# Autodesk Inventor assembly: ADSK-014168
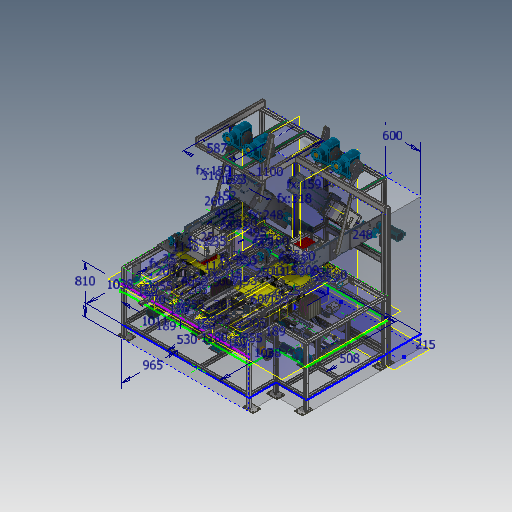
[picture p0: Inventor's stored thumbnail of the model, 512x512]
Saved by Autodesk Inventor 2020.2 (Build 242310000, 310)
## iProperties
Created: 2019-10
Part Number: ADSK-014168
Document SubType Name: Assembly
Designer: lutzd
Mass: 6.6352e+07 g
Surface Area: 1.07155e+06 cm^2
Volume: 8.52523e+06 cm^3
Density: 7.78302 g/cm^3
VLDS_Profile: Default Assembly
VLDS_TimeStamp: 2016-07-29
VLDS_FailCnt: 0
VLDS_AcceptCnt: 0
Dimensions: 2816,7x2637,5x2753,9 mm
Mass: 66352,024 kg
DocNumber: ADSK-014168
Folder: 01 - Themengebiete\Simplification\01 - Packaging machine\
VDS_Category: 3D Komponenten
VDS_NumSchm: Autodesk
Title: MOD-019310
Author: lutzd
Revision Number: -
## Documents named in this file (15)
- D:\07 - DEMODATEN\OTX 2019 - Dataset - UPDATE - Dez2019\Designs\07-Packing machine\ADSK-014168.iam
- D:\07 - DEMODATEN\OTX 2019 - Dataset - UPDATE - Dez2019\Designs\07-Packing machine\ADSK-014078.iam
- D:\07 - DEMODATEN\OTX 2019 - Dataset - UPDATE - Dez2019\Designs\07-Packing machine\SUB-129310.iam
- D:\07 - DEMODATEN\OTX 2019 - Dataset - UPDATE - Dez2019\Content Center Files\de-DE\DIN 125-1  B\DIN 125-1 - B 8,4.ipt
- D:\07 - DEMODATEN\OTX 2019 - Dataset - UPDATE - Dez2019\Content Center Files\de-DE\ISO 4762(2)\ISO 4762 - M8 x 20ISO.ipt
- D:\07 - DEMODATEN\OTX 2019 - Dataset - UPDATE - Dez2019\Designs\07-Packing machine\SUB-139310.iam
- D:\07 - DEMODATEN\OTX 2019 - Dataset - UPDATE - Dez2019\Designs\07-Packing machine\SUB-149310.iam
- D:\07 - DEMODATEN\OTX 2019 - Dataset - UPDATE - Dez2019\Content Center Files\de-DE\ISO 4762(2)\ISO 4762 - M10 x 16ISO.ipt
- D:\07 - DEMODATEN\OTX 2019 - Dataset - UPDATE - Dez2019\Designs\07-Packing machine\ADSK-014171.iam
- D:\07 - DEMODATEN\OTX 2019 - Dataset - UPDATE - Dez2019\Designs\07-Packing machine\SUB-169310.iam
- D:\07 - DEMODATEN\OTX 2019 - Dataset - UPDATE - Dez2019\Designs\07-Packing machine\SUB-199310.iam
- D:\07 - DEMODATEN\OTX 2019 - Dataset - UPDATE - Dez2019\Designs\07-Packing machine\SUB-179310.iam
- D:\07 - DEMODATEN\OTX 2019 - Dataset - UPDATE - Dez2019\Designs\07-Packing machine\ADSK-014224.iam
- D:\07 - DEMODATEN\OTX 2019 - Dataset - UPDATE - Dez2019\Designs\07-Packing machine\Parts\ADSK-014502.ipt
- SUB-179310.iam
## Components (174 placed, 13 different names)
1. ADSK-014078:1 [sub-assembly] — Passend:1, Passend:2, Passend:3, Passend:4, Passend:5, Passend:6, Passend:7, Passend:8, Passend:9, Passend:16, Fluchtend:1, Passend:17, Passend:18, Passend:19, Passend:20, Passend:21, Passend:22, Passend:31, Passend:32, Passend:33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
2. SUB-129310:1 [sub-assembly] — Passend:1, Passend:2, Passend:3, Passend:10, Passend:11, Passend:12, Passend:13, Passend:14, Passend:15, Passend:27, Passend:28, Passend:29, Passend:30, Passend:194
3. SUB-139310:1 [sub-assembly] — Passend:16, Fluchtend:1, Passend:17, Passend:18, Passend:23, Passend:24, Passend:25, Passend:26, Passend:86, Passend:88, Passend:90, Passend:92, Passend:94, Passend:96, Passend:98
4. SUB-149310:1 [sub-assembly] — Passend:35, Passend:36, Passend:37, Passend:192
5. ADSK-014171:1 [sub-assembly] — Passend:38, Passend:39, Passend:40, Passend:42, Passend:44, Passend:46, Passend:48, Passend:58, Passend:60, Passend:184, Passend:185, Passend:186, Passend:187, Passend:190, Passend:191, Passend:193
6. SUB-169310:1 [sub-assembly] — Passend:65, Passend:66, Passend:67, Passend:188, Passend:189
7. SUB-139310:2 [sub-assembly] — Passend:68, Passend:69, Passend:70, Passend:72, Passend:74, Passend:76, Passend:78, Passend:80, Passend:82, Passend:84, Passend:100, Passend:102, Passend:104, Passend:106
8. SUB-199310:1 [sub-assembly] — Fluchtend:2, Passend:107, Passend:108, Passend:124, Passend:126, Passend:132, Passend:134, Passend:144, Passend:146, Passend:148, Passend:150, Passend:152, Passend:154, Passend:156, Passend:158
9. SUB-199310:2 [sub-assembly] — Passend:109, Fluchtend:3, Passend:110, Passend:112, Passend:114, Passend:116, Passend:118, Passend:120, Passend:122, Passend:128, Passend:130, Passend:136, Passend:138, Passend:140, Passend:142
10. SUB-179310:1 [sub-assembly] — Passend:159, Passend:160, Passend:161, Passend:163, Passend:165, Passend:167, Passend:169, Passend:171, Passend:173, Passend:175, Passend:177, Passend:179, Passend:181
11. ADSK-014224:1 [sub-assembly] — Passend:182, Passend:183, Fluchtend:4
12. ADSK-014502:1 — Passend:184, Passend:185, Passend:189
13. ADSK-014502:2 — Passend:186, Passend:187, Passend:188
14. ADSK-014502:3 — Passend:190, Passend:191, Passend:192, Passend:193, Passend:194
15. DIN 125-1 B B 8,4:63 — Passend:163, Einfügen:78
16. DIN 125-1 B B 8,4:64 — Passend:165, Einfügen:77
17. DIN 125-1 B B 8,4:65 — Passend:167, Einfügen:76
18. DIN 125-1 B B 8,4:66 — Passend:169, Einfügen:75
19. DIN 125-1 B B 8,4:67 — Passend:171, Einfügen:74
20. DIN 125-1 B B 8,4:68 — Passend:173, Einfügen:73
21. DIN 125-1 B B 8,4:69 — Passend:175, Einfügen:82
22. DIN 125-1 B B 8,4:70 — Passend:177, Einfügen:81
23. DIN 125-1 B B 8,4:71 — Passend:179, Einfügen:79
24. DIN 125-1 B B 8,4:72 — Passend:181, Einfügen:80
25. ISO 4762 M8 x 20:63 — Einfügen:73
26. ISO 4762 M8 x 20:64 — Einfügen:74
27. ISO 4762 M8 x 20:65 — Einfügen:75
28. ISO 4762 M8 x 20:66 — Einfügen:76
29. ISO 4762 M8 x 20:67 — Einfügen:77
30. ISO 4762 M8 x 20:68 — Einfügen:78
31. ISO 4762 M8 x 20:69 — Einfügen:79
32. ISO 4762 M8 x 20:70 — Einfügen:81
33. ISO 4762 M8 x 20:71 — Einfügen:82
34. ISO 4762 M8 x 20:72 — Einfügen:80
35. DIN 125-1 B B 8,4:39 — Passend:112, Einfügen:61
36. DIN 125-1 B B 8,4:40 — Passend:114, Einfügen:62
37. DIN 125-1 B B 8,4:41 — Passend:116, Einfügen:60
38. DIN 125-1 B B 8,4:42 — Passend:118, Einfügen:59
39. DIN 125-1 B B 8,4:43 — Passend:120, Einfügen:67
40. DIN 125-1 B B 8,4:44 — Passend:122, Einfügen:68
41. DIN 125-1 B B 8,4:45 — Passend:124, Einfügen:53
42. DIN 125-1 B B 8,4:46 — Passend:126, Einfügen:54
43. DIN 125-1 B B 8,4:47 — Passend:128, Einfügen:65
44. DIN 125-1 B B 8,4:48 — Passend:130, Einfügen:66
45. DIN 125-1 B B 8,4:49 — Passend:132, Einfügen:51
46. DIN 125-1 B B 8,4:50 — Passend:134, Einfügen:52
47. DIN 125-1 B B 8,4:51 — Passend:136, Einfügen:71
48. DIN 125-1 B B 8,4:52 — Passend:138, Einfügen:72
49. DIN 125-1 B B 8,4:53 — Passend:140, Einfügen:69
50. DIN 125-1 B B 8,4:54 — Passend:142, Einfügen:70
51. DIN 125-1 B B 8,4:55 — Passend:144, Einfügen:63
52. DIN 125-1 B B 8,4:56 — Passend:146, Einfügen:64
53. DIN 125-1 B B 8,4:57 — Passend:148, Einfügen:49
54. DIN 125-1 B B 8,4:58 — Passend:150, Einfügen:50
55. ISO 4762 M8 x 20:39 — Einfügen:49
56. ISO 4762 M8 x 20:40 — Einfügen:50
57. ISO 4762 M8 x 20:41 — Einfügen:51
58. ISO 4762 M8 x 20:42 — Einfügen:53
59. ISO 4762 M8 x 20:43 — Einfügen:52
60. ISO 4762 M8 x 20:44 — Einfügen:54
61. DIN 125-1 B B 8,4:59 — Passend:152, Einfügen:55
62. DIN 125-1 B B 8,4:60 — Passend:154, Einfügen:56
63. ISO 4762 M8 x 20:45 — Einfügen:55
64. ISO 4762 M8 x 20:46 — Einfügen:56
65. DIN 125-1 B B 8,4:61 — Passend:156, Einfügen:57
66. DIN 125-1 B B 8,4:62 — Passend:158, Einfügen:58
67. ISO 4762 M8 x 20:47 — Einfügen:57
68. ISO 4762 M8 x 20:48 — Einfügen:58
69. ISO 4762 M8 x 20:49 — Einfügen:59
70. ISO 4762 M8 x 20:50 — Einfügen:60
71. ISO 4762 M8 x 20:51 — Einfügen:61
72. ISO 4762 M8 x 20:52 — Einfügen:62
73. ISO 4762 M8 x 20:53 — Einfügen:63
74. ISO 4762 M8 x 20:54 — Einfügen:64
75. ISO 4762 M8 x 20:55 — Einfügen:65
76. ISO 4762 M8 x 20:56 — Einfügen:67
77. ISO 4762 M8 x 20:57 — Einfügen:66
78. ISO 4762 M8 x 20:58 — Einfügen:68
79. ISO 4762 M8 x 20:59 — Einfügen:69
80. ISO 4762 M8 x 20:60 — Einfügen:70
81. ISO 4762 M8 x 20:61 — Einfügen:72
82. ISO 4762 M8 x 20:62 — Einfügen:71
83. DIN 125-1 B B 8,4:31 — Passend:92, Einfügen:41
84. DIN 125-1 B B 8,4:32 — Passend:94, Einfügen:42
85. DIN 125-1 B B 8,4:33 — Passend:96, Einfügen:43
86. DIN 125-1 B B 8,4:34 — Passend:98, Einfügen:44
87. ISO 4762 M8 x 20:31 — Einfügen:41
88. ISO 4762 M8 x 20:32 — Einfügen:42
89. ISO 4762 M8 x 20:33 — Einfügen:43
90. ISO 4762 M8 x 20:34 — Einfügen:44
91. DIN 125-1 B B 8,4:35 — Passend:100, Einfügen:45
92. DIN 125-1 B B 8,4:36 — Passend:102, Einfügen:46
93. DIN 125-1 B B 8,4:37 — Passend:104, Einfügen:47
94. DIN 125-1 B B 8,4:38 — Passend:106, Einfügen:48
95. ISO 4762 M8 x 20:35 — Einfügen:45
96. ISO 4762 M8 x 20:36 — Einfügen:46
97. ISO 4762 M8 x 20:37 — Einfügen:47
98. ISO 4762 M8 x 20:38 — Einfügen:48
99. DIN 125-1 B B 8,4:21 — Passend:72, Einfügen:34
100. DIN 125-1 B B 8,4:22 — Passend:74, Einfügen:35
101. DIN 125-1 B B 8,4:23 — Passend:76, Einfügen:36
102. DIN 125-1 B B 8,4:24 — Passend:78, Einfügen:37
103. DIN 125-1 B B 8,4:25 — Passend:80, Einfügen:38
104. DIN 125-1 B B 8,4:26 — Passend:82, Einfügen:40
105. DIN 125-1 B B 8,4:27 — Passend:84, Einfügen:39
106. DIN 125-1 B B 8,4:28 — Passend:86, Einfügen:31
107. DIN 125-1 B B 8,4:29 — Passend:88, Einfügen:32
108. DIN 125-1 B B 8,4:30 — Passend:90, Einfügen:33
109. ISO 4762 M8 x 20:21 — Einfügen:31
110. ISO 4762 M8 x 20:22 — Einfügen:32
111. ISO 4762 M8 x 20:23 — Einfügen:33
112. ISO 4762 M8 x 20:24 — Einfügen:34
113. ISO 4762 M8 x 20:25 — Einfügen:35
114. ISO 4762 M8 x 20:26 — Einfügen:36
115. ISO 4762 M8 x 20:27 — Einfügen:37
116. ISO 4762 M8 x 20:28 — Einfügen:38
117. ISO 4762 M8 x 20:29 — Einfügen:39
118. ISO 4762 M8 x 20:30 — Einfügen:40
119. ISO 4762 M10 x 16:7
120. ISO 4762 M10 x 16:8
121. ISO 4762 M10 x 16:9
122. ISO 4762 M10 x 16:10
123. ISO 4762 M10 x 16:11
124. ISO 4762 M10 x 16:12
125. ISO 4762 M10 x 16:13
126. ISO 4762 M10 x 16:14
127. ISO 4762 M10 x 16:15
128. ISO 4762 M10 x 16:16
129. DIN 125-1 B B 8,4:19 — Passend:58, Passend:62
130. DIN 125-1 B B 8,4:20 — Passend:60, Passend:64
131. ISO 4762 M8 x 20:19 — Passend:62
132. ISO 4762 M8 x 20:20 — Passend:64
133. DIN 125-1 B B 8,4:15 — Passend:42, Passend:54, Passend:56
134. DIN 125-1 B B 8,4:16 — Passend:44
135. DIN 125-1 B B 8,4:17 — Passend:46, Passend:50, Passend:52
136. DIN 125-1 B B 8,4:18 — Passend:48
137. ISO 4762 M8 x 20:15 — Passend:50
138. ISO 4762 M8 x 20:16 — Passend:52
139. ISO 4762 M8 x 20:17 — Passend:54
140. ISO 4762 M8 x 20:18 — Passend:56
141. ISO 4762 M10 x 16:1
142. ISO 4762 M10 x 16:2
143. ISO 4762 M10 x 16:3
144. ISO 4762 M10 x 16:4
145. ISO 4762 M10 x 16:5
146. ISO 4762 M10 x 16:6
147. DIN 125-1 B B 8,4:11 — Passend:27
148. ISO 4762 M8 x 20:11 — Passend:34
149. DIN 125-1 B B 8,4:12 — Passend:28
150. ISO 4762 M8 x 20:12 — Passend:33
151. DIN 125-1 B B 8,4:13 — Passend:29
152. ISO 4762 M8 x 20:13 — Passend:32
153. DIN 125-1 B B 8,4:14 — Passend:30
154. ISO 4762 M8 x 20:14 — Passend:31
155. DIN 125-1 B B 8,4:1 — Einfügen:1, Passend:13
156. ISO 4762 M8 x 20:1 — Einfügen:1, Passend:4
157. DIN 125-1 B B 8,4:2 — Passend:12
158. ISO 4762 M8 x 20:2 — Passend:7
159. DIN 125-1 B B 8,4:3 — Passend:14
160. ISO 4762 M8 x 20:3 — Passend:5
161. DIN 125-1 B B 8,4:4 — Passend:11
162. ISO 4762 M8 x 20:4 — Passend:8
163. DIN 125-1 B B 8,4:5 — Passend:10
164. ISO 4762 M8 x 20:5 — Passend:9
165. DIN 125-1 B B 8,4:6 — Passend:15
166. ISO 4762 M8 x 20:6 — Passend:6
167. DIN 125-1 B B 8,4:7 — Passend:25
168. ISO 4762 M8 x 20:7 — Passend:19
169. DIN 125-1 B B 8,4:8 — Passend:24
170. ISO 4762 M8 x 20:8 — Passend:20
171. DIN 125-1 B B 8,4:9 — Passend:26
172. ISO 4762 M8 x 20:9 — Passend:22
173. DIN 125-1 B B 8,4:10 — Passend:23
174. ISO 4762 M8 x 20:10 — Passend:21
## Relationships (187: Mate 130, Insert 53, Flush 4)
- Passend:1 [Mate]: ADSK-014078:1 ↔ SUB-129310:1
- Passend:2 [Mate]: ADSK-014078:1 ↔ SUB-129310:1
- Passend:3 [Mate]: ADSK-014078:1 ↔ SUB-129310:1
- Einfügen:1 [Insert]: DIN 125-1 B B 8,4:1 ↔ ISO 4762 M8 x 20:1
- Passend:4 [Mate]: ADSK-014078:1 ↔ ISO 4762 M8 x 20:1
- Passend:5 [Mate]: ADSK-014078:1 ↔ ISO 4762 M8 x 20:3
- Passend:6 [Mate]: ADSK-014078:1 ↔ ISO 4762 M8 x 20:6
- Passend:7 [Mate]: ADSK-014078:1 ↔ ISO 4762 M8 x 20:2
- Passend:8 [Mate]: ADSK-014078:1 ↔ ISO 4762 M8 x 20:4
- Passend:9 [Mate]: ADSK-014078:1 ↔ ISO 4762 M8 x 20:5
- Passend:10 [Mate]: SUB-129310:1 ↔ DIN 125-1 B B 8,4:5
- Passend:11 [Mate]: SUB-129310:1 ↔ DIN 125-1 B B 8,4:4
- Passend:12 [Mate]: SUB-129310:1 ↔ DIN 125-1 B B 8,4:2
- Passend:13 [Mate]: SUB-129310:1 ↔ DIN 125-1 B B 8,4:1
- Passend:14 [Mate]: SUB-129310:1 ↔ DIN 125-1 B B 8,4:3
- Passend:15 [Mate]: SUB-129310:1 ↔ DIN 125-1 B B 8,4:6
- Passend:16 [Mate]: ADSK-014078:1 ↔ SUB-139310:1
- Fluchtend:1 [Flush]: ADSK-014078:1 ↔ SUB-139310:1
- Passend:17 [Mate]: ADSK-014078:1 ↔ SUB-139310:1
- Passend:18 [Mate]: ADSK-014078:1 ↔ SUB-139310:1
- Passend:19 [Mate]: ADSK-014078:1 ↔ ISO 4762 M8 x 20:7
- Passend:20 [Mate]: ADSK-014078:1 ↔ ISO 4762 M8 x 20:8
- Passend:21 [Mate]: ADSK-014078:1 ↔ ISO 4762 M8 x 20:10
- Passend:22 [Mate]: ADSK-014078:1 ↔ ISO 4762 M8 x 20:9
- Passend:23 [Mate]: SUB-139310:1 ↔ DIN 125-1 B B 8,4:10
- Passend:24 [Mate]: SUB-139310:1 ↔ DIN 125-1 B B 8,4:8
- Passend:25 [Mate]: SUB-139310:1 ↔ DIN 125-1 B B 8,4:7
- Passend:26 [Mate]: SUB-139310:1 ↔ DIN 125-1 B B 8,4:9
- Passend:27 [Mate]: SUB-129310:1 ↔ DIN 125-1 B B 8,4:11
- Passend:28 [Mate]: SUB-129310:1 ↔ DIN 125-1 B B 8,4:12
- Passend:29 [Mate]: SUB-129310:1 ↔ DIN 125-1 B B 8,4:13
- Passend:30 [Mate]: SUB-129310:1 ↔ DIN 125-1 B B 8,4:14
- Passend:31 [Mate]: ADSK-014078:1 ↔ ISO 4762 M8 x 20:14
- Passend:32 [Mate]: ADSK-014078:1 ↔ ISO 4762 M8 x 20:13
- Passend:33 [Mate]: ADSK-014078:1 ↔ ISO 4762 M8 x 20:12
- Passend:34 [Mate]: ADSK-014078:1 ↔ ISO 4762 M8 x 20:11
- Passend:35 [Mate]: ADSK-014078:1 ↔ SUB-149310:1
- Passend:36 [Mate]: ADSK-014078:1 ↔ SUB-149310:1
- Passend:37 [Mate]: ADSK-014078:1 ↔ SUB-149310:1
- Passend:38 [Mate]: ADSK-014078:1 ↔ ADSK-014171:1
- Passend:39 [Mate]: ADSK-014078:1 ↔ ADSK-014171:1
- Passend:40 [Mate]: ADSK-014078:1 ↔ ADSK-014171:1
- Passend:42 [Mate]: ADSK-014171:1 ↔ DIN 125-1 B B 8,4:15
- Passend:44 [Mate]: ADSK-014171:1 ↔ DIN 125-1 B B 8,4:16
- Passend:46 [Mate]: ADSK-014171:1 ↔ DIN 125-1 B B 8,4:17
- Passend:48 [Mate]: ADSK-014171:1 ↔ DIN 125-1 B B 8,4:18
- Passend:50 [Mate]: DIN 125-1 B B 8,4:17 ↔ ISO 4762 M8 x 20:15
- Passend:52 [Mate]: DIN 125-1 B B 8,4:17 ↔ ISO 4762 M8 x 20:16
- Passend:54 [Mate]: DIN 125-1 B B 8,4:15 ↔ ISO 4762 M8 x 20:17
- Passend:56 [Mate]: DIN 125-1 B B 8,4:15 ↔ ISO 4762 M8 x 20:18
- Passend:58 [Mate]: ADSK-014171:1 ↔ DIN 125-1 B B 8,4:19
- Passend:60 [Mate]: ADSK-014171:1 ↔ DIN 125-1 B B 8,4:20
- Passend:62 [Mate]: DIN 125-1 B B 8,4:19 ↔ ISO 4762 M8 x 20:19
- Passend:64 [Mate]: DIN 125-1 B B 8,4:20 ↔ ISO 4762 M8 x 20:20
- Passend:65 [Mate]: ADSK-014078:1 ↔ SUB-169310:1
- Passend:66 [Mate]: ADSK-014078:1 ↔ SUB-169310:1
- Passend:67 [Mate]: ADSK-014078:1 ↔ SUB-169310:1
- Passend:68 [Mate]: ADSK-014078:1 ↔ SUB-139310:2
- Passend:69 [Mate]: ADSK-014078:1 ↔ SUB-139310:2
- Passend:70 [Mate]: ADSK-014078:1 ↔ SUB-139310:2
- Passend:72 [Mate]: SUB-139310:2 ↔ DIN 125-1 B B 8,4:21
- Passend:74 [Mate]: SUB-139310:2 ↔ DIN 125-1 B B 8,4:22
- Passend:76 [Mate]: SUB-139310:2 ↔ DIN 125-1 B B 8,4:23
- Passend:78 [Mate]: SUB-139310:2 ↔ DIN 125-1 B B 8,4:24
- Passend:80 [Mate]: SUB-139310:2 ↔ DIN 125-1 B B 8,4:25
- Passend:82 [Mate]: SUB-139310:2 ↔ DIN 125-1 B B 8,4:26
- Passend:84 [Mate]: SUB-139310:2 ↔ DIN 125-1 B B 8,4:27
- Passend:86 [Mate]: SUB-139310:1 ↔ DIN 125-1 B B 8,4:28
- Passend:88 [Mate]: SUB-139310:1 ↔ DIN 125-1 B B 8,4:29
- Passend:90 [Mate]: SUB-139310:1 ↔ DIN 125-1 B B 8,4:30
- Einfügen:31 [Insert]: DIN 125-1 B B 8,4:28 ↔ ISO 4762 M8 x 20:21
- Einfügen:32 [Insert]: DIN 125-1 B B 8,4:29 ↔ ISO 4762 M8 x 20:22
- Einfügen:33 [Insert]: DIN 125-1 B B 8,4:30 ↔ ISO 4762 M8 x 20:23
- Einfügen:34 [Insert]: DIN 125-1 B B 8,4:21 ↔ ISO 4762 M8 x 20:24
- Einfügen:35 [Insert]: DIN 125-1 B B 8,4:22 ↔ ISO 4762 M8 x 20:25
- Einfügen:36 [Insert]: DIN 125-1 B B 8,4:23 ↔ ISO 4762 M8 x 20:26
- Einfügen:37 [Insert]: DIN 125-1 B B 8,4:24 ↔ ISO 4762 M8 x 20:27
- Einfügen:38 [Insert]: DIN 125-1 B B 8,4:25 ↔ ISO 4762 M8 x 20:28
- Einfügen:39 [Insert]: DIN 125-1 B B 8,4:27 ↔ ISO 4762 M8 x 20:29
- Einfügen:40 [Insert]: DIN 125-1 B B 8,4:26 ↔ ISO 4762 M8 x 20:30
- Passend:92 [Mate]: SUB-139310:1 ↔ DIN 125-1 B B 8,4:31
- Passend:94 [Mate]: SUB-139310:1 ↔ DIN 125-1 B B 8,4:32
- Passend:96 [Mate]: SUB-139310:1 ↔ DIN 125-1 B B 8,4:33
- Passend:98 [Mate]: SUB-139310:1 ↔ DIN 125-1 B B 8,4:34
- Einfügen:41 [Insert]: DIN 125-1 B B 8,4:31 ↔ ISO 4762 M8 x 20:31
- Einfügen:42 [Insert]: DIN 125-1 B B 8,4:32 ↔ ISO 4762 M8 x 20:32
- Einfügen:43 [Insert]: DIN 125-1 B B 8,4:33 ↔ ISO 4762 M8 x 20:33
- Einfügen:44 [Insert]: DIN 125-1 B B 8,4:34 ↔ ISO 4762 M8 x 20:34
- Passend:100 [Mate]: SUB-139310:2 ↔ DIN 125-1 B B 8,4:35
- Passend:102 [Mate]: SUB-139310:2 ↔ DIN 125-1 B B 8,4:36
- Passend:104 [Mate]: SUB-139310:2 ↔ DIN 125-1 B B 8,4:37
- Passend:106 [Mate]: SUB-139310:2 ↔ DIN 125-1 B B 8,4:38
- Einfügen:45 [Insert]: DIN 125-1 B B 8,4:35 ↔ ISO 4762 M8 x 20:35
- Einfügen:46 [Insert]: DIN 125-1 B B 8,4:36 ↔ ISO 4762 M8 x 20:36
- Einfügen:47 [Insert]: DIN 125-1 B B 8,4:37 ↔ ISO 4762 M8 x 20:37
- Einfügen:48 [Insert]: DIN 125-1 B B 8,4:38 ↔ ISO 4762 M8 x 20:38
- Fluchtend:2 [Flush]: ADSK-014078:1 ↔ SUB-199310:1
- Passend:107 [Mate]: ADSK-014078:1 ↔ SUB-199310:1
- Passend:108 [Mate]: ADSK-014078:1 ↔ SUB-199310:1
- Passend:109 [Mate]: ADSK-014078:1 ↔ SUB-199310:2
- Fluchtend:3 [Flush]: ADSK-014078:1 ↔ SUB-199310:2
- Passend:110 [Mate]: ADSK-014078:1 ↔ SUB-199310:2
- Passend:112 [Mate]: SUB-199310:2 ↔ DIN 125-1 B B 8,4:39
- Passend:114 [Mate]: SUB-199310:2 ↔ DIN 125-1 B B 8,4:40
- Passend:116 [Mate]: SUB-199310:2 ↔ DIN 125-1 B B 8,4:41
- Passend:118 [Mate]: SUB-199310:2 ↔ DIN 125-1 B B 8,4:42
- Passend:120 [Mate]: SUB-199310:2 ↔ DIN 125-1 B B 8,4:43
- Passend:122 [Mate]: SUB-199310:2 ↔ DIN 125-1 B B 8,4:44
- Passend:124 [Mate]: SUB-199310:1 ↔ DIN 125-1 B B 8,4:45
- Passend:126 [Mate]: SUB-199310:1 ↔ DIN 125-1 B B 8,4:46
- Passend:128 [Mate]: SUB-199310:2 ↔ DIN 125-1 B B 8,4:47
- Passend:130 [Mate]: SUB-199310:2 ↔ DIN 125-1 B B 8,4:48
- Passend:132 [Mate]: SUB-199310:1 ↔ DIN 125-1 B B 8,4:49
- Passend:134 [Mate]: SUB-199310:1 ↔ DIN 125-1 B B 8,4:50
- Passend:136 [Mate]: SUB-199310:2 ↔ DIN 125-1 B B 8,4:51
- Passend:138 [Mate]: SUB-199310:2 ↔ DIN 125-1 B B 8,4:52
- Passend:140 [Mate]: SUB-199310:2 ↔ DIN 125-1 B B 8,4:53
- Passend:142 [Mate]: SUB-199310:2 ↔ DIN 125-1 B B 8,4:54
- Passend:144 [Mate]: SUB-199310:1 ↔ DIN 125-1 B B 8,4:55
- Passend:146 [Mate]: SUB-199310:1 ↔ DIN 125-1 B B 8,4:56
- Passend:148 [Mate]: SUB-199310:1 ↔ DIN 125-1 B B 8,4:57
- Passend:150 [Mate]: SUB-199310:1 ↔ DIN 125-1 B B 8,4:58
- Einfügen:49 [Insert]: DIN 125-1 B B 8,4:57 ↔ ISO 4762 M8 x 20:39
- Einfügen:50 [Insert]: DIN 125-1 B B 8,4:58 ↔ ISO 4762 M8 x 20:40
- Einfügen:51 [Insert]: DIN 125-1 B B 8,4:49 ↔ ISO 4762 M8 x 20:41
- Einfügen:52 [Insert]: DIN 125-1 B B 8,4:50 ↔ ISO 4762 M8 x 20:43
- Einfügen:53 [Insert]: DIN 125-1 B B 8,4:45 ↔ ISO 4762 M8 x 20:42
- Einfügen:54 [Insert]: DIN 125-1 B B 8,4:46 ↔ ISO 4762 M8 x 20:44
- Passend:152 [Mate]: SUB-199310:1 ↔ DIN 125-1 B B 8,4:59
- Passend:154 [Mate]: SUB-199310:1 ↔ DIN 125-1 B B 8,4:60
- Einfügen:55 [Insert]: DIN 125-1 B B 8,4:59 ↔ ISO 4762 M8 x 20:45
- Einfügen:56 [Insert]: DIN 125-1 B B 8,4:60 ↔ ISO 4762 M8 x 20:46
- Passend:156 [Mate]: SUB-199310:1 ↔ DIN 125-1 B B 8,4:61
- Passend:158 [Mate]: SUB-199310:1 ↔ DIN 125-1 B B 8,4:62
- Einfügen:57 [Insert]: DIN 125-1 B B 8,4:61 ↔ ISO 4762 M8 x 20:47
- Einfügen:58 [Insert]: DIN 125-1 B B 8,4:62 ↔ ISO 4762 M8 x 20:48
- Einfügen:59 [Insert]: DIN 125-1 B B 8,4:42 ↔ ISO 4762 M8 x 20:49
- Einfügen:60 [Insert]: DIN 125-1 B B 8,4:41 ↔ ISO 4762 M8 x 20:50
- Einfügen:61 [Insert]: DIN 125-1 B B 8,4:39 ↔ ISO 4762 M8 x 20:51
- Einfügen:62 [Insert]: DIN 125-1 B B 8,4:40 ↔ ISO 4762 M8 x 20:52
- Einfügen:63 [Insert]: DIN 125-1 B B 8,4:55 ↔ ISO 4762 M8 x 20:53
- Einfügen:64 [Insert]: DIN 125-1 B B 8,4:56 ↔ ISO 4762 M8 x 20:54
- Einfügen:65 [Insert]: DIN 125-1 B B 8,4:47 ↔ ISO 4762 M8 x 20:55
- Einfügen:66 [Insert]: DIN 125-1 B B 8,4:48 ↔ ISO 4762 M8 x 20:57
- Einfügen:67 [Insert]: DIN 125-1 B B 8,4:43 ↔ ISO 4762 M8 x 20:56
- Einfügen:68 [Insert]: DIN 125-1 B B 8,4:44 ↔ ISO 4762 M8 x 20:58
- Einfügen:69 [Insert]: DIN 125-1 B B 8,4:53 ↔ ISO 4762 M8 x 20:59
- Einfügen:70 [Insert]: DIN 125-1 B B 8,4:54 ↔ ISO 4762 M8 x 20:60
- Einfügen:71 [Insert]: DIN 125-1 B B 8,4:51 ↔ ISO 4762 M8 x 20:62
- Einfügen:72 [Insert]: DIN 125-1 B B 8,4:52 ↔ ISO 4762 M8 x 20:61
- Passend:159 [Mate]: ADSK-014078:1 ↔ SUB-179310:1
- Passend:160 [Mate]: ADSK-014078:1 ↔ SUB-179310:1
- Passend:161 [Mate]: ADSK-014078:1 ↔ SUB-179310:1
- Passend:163 [Mate]: SUB-179310:1 ↔ DIN 125-1 B B 8,4:63
- Passend:165 [Mate]: SUB-179310:1 ↔ DIN 125-1 B B 8,4:64
- Passend:167 [Mate]: SUB-179310:1 ↔ DIN 125-1 B B 8,4:65
- Passend:169 [Mate]: SUB-179310:1 ↔ DIN 125-1 B B 8,4:66
- Passend:171 [Mate]: SUB-179310:1 ↔ DIN 125-1 B B 8,4:67
- Passend:173 [Mate]: SUB-179310:1 ↔ DIN 125-1 B B 8,4:68
- Passend:175 [Mate]: SUB-179310:1 ↔ DIN 125-1 B B 8,4:69
- Passend:177 [Mate]: SUB-179310:1 ↔ DIN 125-1 B B 8,4:70
- Passend:179 [Mate]: SUB-179310:1 ↔ DIN 125-1 B B 8,4:71
- Passend:181 [Mate]: SUB-179310:1 ↔ DIN 125-1 B B 8,4:72
- Einfügen:73 [Insert]: DIN 125-1 B B 8,4:68 ↔ ISO 4762 M8 x 20:63
- Einfügen:74 [Insert]: DIN 125-1 B B 8,4:67 ↔ ISO 4762 M8 x 20:64
- Einfügen:75 [Insert]: DIN 125-1 B B 8,4:66 ↔ ISO 4762 M8 x 20:65
- Einfügen:76 [Insert]: DIN 125-1 B B 8,4:65 ↔ ISO 4762 M8 x 20:66
- Einfügen:77 [Insert]: DIN 125-1 B B 8,4:64 ↔ ISO 4762 M8 x 20:67
- Einfügen:78 [Insert]: DIN 125-1 B B 8,4:63 ↔ ISO 4762 M8 x 20:68
- Einfügen:79 [Insert]: DIN 125-1 B B 8,4:71 ↔ ISO 4762 M8 x 20:69
- Einfügen:80 [Insert]: DIN 125-1 B B 8,4:72 ↔ ISO 4762 M8 x 20:72
- Einfügen:81 [Insert]: DIN 125-1 B B 8,4:70 ↔ ISO 4762 M8 x 20:70
- Einfügen:82 [Insert]: DIN 125-1 B B 8,4:69 ↔ ISO 4762 M8 x 20:71
- Passend:182 [Mate]: ADSK-014224:1
- Passend:183 [Mate]: ADSK-014078:1 ↔ ADSK-014224:1
- Fluchtend:4 [Flush]: ADSK-014078:1 ↔ ADSK-014224:1
- Passend:184 [Mate]: ADSK-014171:1 ↔ ADSK-014502:1
- Passend:185 [Mate]: ADSK-014171:1 ↔ ADSK-014502:1
- Passend:186 [Mate]: ADSK-014171:1 ↔ ADSK-014502:2
- Passend:187 [Mate]: ADSK-014171:1 ↔ ADSK-014502:2
- Passend:188 [Mate]: SUB-169310:1 ↔ ADSK-014502:2
- Passend:189 [Mate]: SUB-169310:1 ↔ ADSK-014502:1
- Passend:190 [Mate]: ADSK-014171:1 ↔ ADSK-014502:3
- Passend:191 [Mate]: ADSK-014171:1 ↔ ADSK-014502:3
- Passend:192 [Mate]: SUB-149310:1 ↔ ADSK-014502:3
- Passend:193 [Mate]: ADSK-014171:1 ↔ ADSK-014502:3
- Passend:194 [Mate]: SUB-129310:1 ↔ ADSK-014502:3
## Named parameters: d4_d3 = 0, d5_d3 = 0, d6_d3 = 0, d7_d3 = 0, d8_d3 = 0, d25_d7_d3 = 0, d26_d7_d3 = 0, d27_d7_d3 = 0, d28_d7_d3 = 0, d37_d3 = 0, d38_d3 = 0, d39_d3 = 0, d40_d3 = 0
